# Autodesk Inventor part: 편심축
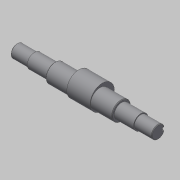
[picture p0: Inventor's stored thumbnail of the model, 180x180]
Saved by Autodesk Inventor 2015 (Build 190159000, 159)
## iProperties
Created: 2015-10
Part Number: 편심축
Document SubType Name: Modeling
Designer: mdu
Density: 7.86 g/cm^3
Material: 강철, 연강
Mass: 1327.93 g
Surface Area: 248.524 cm^2
Volume: 168.947 cm^3
Appearance: 강철
Author: mdu
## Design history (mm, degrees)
sketch "스케치1"
  geometry: L1 (-20.5, -41.331)-(-20.5, 32.669) reference; L2 (7.5, -30.031)-(7.5, 21.369) reference; L3 (135.5, -30.331)-(135.5, 21.669) reference; L4 (121.5, 21.369)-(121.5, -30.031) reference; L5 (184.5, -4.331)-(-57.5, -4.331); L6 (184.5, -4.331)-(184.5, 6.669); L7 (154.5, 8.169)-(121.5, 8.169); L8 (121.5, 8.169)-(121.5, 11.669); L9 (121.5, 11.669)-(7.5, 11.669); L10 (7.5, 11.669)-(7.5, 8.169); L11 (7.5, 8.169)-(-27.5, 8.169); L12 (-27.5, 8.169)-(-27.5, 6.669); L13 (-27.5, 6.669)-(-57.5, 6.669); L14 (-57.5, 6.669)-(-57.5, -4.331); L15 (154.5, 8.169)-(154.5, 6.669); L16 (154.5, 6.669)-(184.5, 6.669); C1 r 32.5 at (64.5, -4.331) reference; 1 further point
  constraints: 24 end point, 8 perpendicular, 5 point on line, 3 parallel, 2 collinear
  dimensions: "d1" = 25 diameter of L11 L5; "d2" = 32 diameter of L9 L5; "d3" = 22 diameter of L13 L5; "d4" = 35 distance of L10.end L11.end; "d5" = 30 distance of L12.end L13.end; "d15" = 33 distance of L7.start L7.end; "d26" = 30 distance of L15.end L6.end
revolve "회전1" sketch "스케치1" stored, may be unused: angle "d6" = 90 deg
node "작업 평면1"
sketch "스케치2"
  geometry: C1 r 16 at (0, 0) reference; C2 r 16 at (0, 0) reference; C3 r 20.75 at (0, 4); C4 r 16 at (0, 0) reference; 1 further point
  constraints: 1 centre point, 1 vertical alignment
  dimensions: "d8" = 41.5 diameter of C3; "d25" = 4 distance of C3.centre C1.centre
extrude "돌출1" join sketch "스케치2" stored distance "d9" = 40; taper "d10" = 0 deg
chamfer "모따기1" distance "d11" = 1; stored, may be unused: second distance "d12" = 2, angle "d13" = 45 deg
node "작업 평면2"
sketch "스케치3"
  geometry: L1 (-15, -10)-(-15, 10) reference; L2 (-15, 3)-(0, 3); L3 (0, -3)-(-15, -3); A1 r 3 centre (0, 0) between (0, -3) and (0, 3); 2 further points
  constraints: 4 end point, 2 perpendicular, 2 point on circle, 2 point on line, 2 tangent, 1 centre point, 1 horizontal alignment, 1 midpoint
  dimensions: "d16" = 18 dimension on A1 L1; "d17" = 6 distance between parallel lines of L3 L2
extrude "돌출2" cut sketch "스케치3" distance "d18" = 3.5; taper "d19" = 0 deg
node "작업 평면3"
node "솔리드1"
mirror "대칭1"
node "참조1"
node "참조2"
node "참조3"
node "참조4"
node "참조5"
node "투영된 루프1"
